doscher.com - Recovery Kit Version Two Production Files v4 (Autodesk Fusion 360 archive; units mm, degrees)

design "doscher.com - Recovery Kit Version Two Production Files" references "6168T59_Push-In Signal Power Connectors(1)", "6886K111_Flush-Mount 16 mm Panel-Mount Push-Button Switch", "1422N13_Panel-Mount Data Adapter"
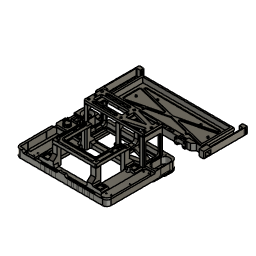
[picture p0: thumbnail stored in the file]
parameter "d91" = 8.5
parameter "d92" = -6
parameter "d93" = 0
parameter "d94" = 3
parameter "d95" = 2
parameter "d96" = 3
parameter "d97" = 0
parameter "d98" = 11
parameter "d99" = -35
parameter "d100" = 0
parameter "d101" = -8.951
parameter "d102" = 7
parameter "d103" = -3
parameter "d104" = 0
parameter "d105" = -35
parameter "d106" = 2.8
parameter "d107" = 2.8
parameter "d108" = -70
parameter "d109" = 0
parameter "d110" = 2
parameter "d111" = 2
parameter "d112" = -10
parameter "d113" = 0
parameter "d114" = -5
parameter "d115" = 0
parameter "d116" = -10
parameter "d117" = 0
parameter "d118" = -10
parameter "d119" = 0
parameter "d120" = -2
parameter "d121" = 0
parameter "d122" = 5
parameter "d124" = 0.1
parameter "d126" = 0.1
parameter "d128" = 0.1
parameter "d129" = -4
parameter "d130" = 0
parameter "d131" = 6
parameter "d132" = 0
parameter "d133" = 6
parameter "d134" = 0
parameter "d135" = -3
parameter "d136" = 0
parameter "d137" = 2
parameter "d138" = 0
parameter "d139" = 2
parameter "d140" = 0
parameter "d141" = -4
parameter "d142" = 0
parameter "d143" = 2
parameter "d144" = 0
parameter "d145" = -35
parameter "d146" = 3.8
parameter "d147" = -35
parameter "d148" = 3.8
parameter "d149" = 2.8
parameter "d150" = -20
parameter "d151" = 0
parameter "d152" = 2.8
parameter "d153" = -15
parameter "d154" = 0
parameter "d155" = -54
parameter "d156" = 2.8
parameter "d157" = 51
parameter "d158" = 2.8
parameter "d159" = -54
parameter "d160" = 2.8
parameter "d161" = 62
parameter "d162" = 2.8
parameter "d163" = 90
parameter "d164" = 3.8
parameter "d165" = 100
parameter "d166" = 3.8
parameter "d167" = 2.8
parameter "d168" = -57
parameter "d169" = 0
parameter "d170" = 2
parameter "d171" = 1
parameter "d172" = 20
parameter "d173" = 1
parameter "d174" = 20
parameter "d175" = 1
parameter "d176" = -19
parameter "d177" = 0
parameter "d178" = 59
parameter "d179" = 49.5
parameter "d180" = 59
parameter "d182" = 3
parameter "d183" = 3
parameter "d184" = 9
parameter "d185" = 55.5
parameter "d186" = 3
parameter "d187" = 55.5
parameter "d188" = 10
parameter "d189" = 0
parameter "d190" = 3
parameter "d191" = 3
parameter "d192" = 3
parameter "d193" = 3
parameter "d194" = 3
parameter "d195" = 0
parameter "d196" = -6
parameter "d197" = 0
parameter "d198" = -3
parameter "d199" = 0
parameter "d201" = 3
parameter "d203" = 2
parameter "d204" = 2
parameter "d205" = 5
parameter "d206" = 10
parameter "d207" = 5
parameter "d208" = 10
parameter "d209" = 10
parameter "d210" = 10
parameter "d211" = 10
parameter "d212" = 10
parameter "d213" = 2.8
parameter "d214" = 2.8
parameter "d215" = 2.8
parameter "d216" = -84
parameter "d217" = 0
parameter "d218" = 1
parameter "d219" = 0
parameter "d220" = 2
parameter "d221" = 2
parameter "d222" = 2
parameter "d223" = 2
parameter "d224" = -2
parameter "d225" = -2
parameter "d226" = -2
parameter "d227" = 2.8
parameter "d228" = -2
parameter "d229" = 2.8
parameter "d230" = -2
parameter "d231" = 2.8
parameter "d233" = 7.5
parameter "d235" = 7.5
parameter "d237" = 3.25
parameter "d238" = -1
parameter "d239" = 2.8
parameter "d240" = -1
parameter "d241" = 2.8
parameter "d243" = 8
parameter "d245" = 8
parameter "d246" = -1
parameter "d247" = 2.8
parameter "d248" = -15
parameter "d249" = 0
parameter "d251" = 0.1
parameter "d252" = 16
parameter "d253" = 4
parameter "d254" = 3
parameter "d255" = 8
parameter "d256" = -5
parameter "d257" = 0
parameter "d259" = 1
parameter "d261" = 1
parameter "d262" = 51.5
parameter "d263" = 158
parameter "d264" = 2
parameter "d265" = 0
parameter "d266" = 10
parameter "d267" = 26
parameter "d268" = -4
parameter "d269" = 0
parameter "d270" = 1
parameter "d271" = 3
parameter "d272" = 50
parameter "d273" = 2.8
parameter "d274" = 24
parameter "d275" = 3
parameter "d276" = 50
parameter "d277" = 3
parameter "d278" = 50
parameter "d279" = 3
parameter "d280" = 50
parameter "d281" = 3
parameter "d282" = 26
parameter "d283" = 3
parameter "d284" = 50
parameter "d285" = 3
parameter "d286" = 50
parameter "d287" = 3
parameter "d288" = 30
parameter "d289" = 3
parameter "d290" = 50
parameter "d291" = 3
parameter "d292" = 10
parameter "d293" = 10
parameter "d294" = 10
parameter "d295" = 10
parameter "d296" = 10
parameter "d297" = 10
parameter "d298" = 10
parameter "d299" = 10
parameter "d300" = 10
parameter "d301" = 10
parameter "d302" = 10
parameter "d303" = 10
parameter "d304" = 10
parameter "d305" = 10
parameter "d306" = 10
parameter "d307" = 10
parameter "d308" = 10
parameter "d309" = 10
parameter "d310" = 3
parameter "d311" = -10
parameter "d312" = 0
parameter "d313" = 1
parameter "d314" = 0
parameter "d315" = 2
parameter "d316" = 2
parameter "d317" = 3
parameter "d318" = 0
parameter "d319" = -3
parameter "d320" = 6
parameter "d321" = -3
parameter "d322" = 6
parameter "d323" = -3
parameter "d324" = 6
parameter "d325" = -3
parameter "d326" = 6
parameter "d327" = -3
parameter "d328" = 6
parameter "d329" = -3
parameter "d330" = 6
parameter "d331" = -3
parameter "d332" = 6
parameter "d333" = -3
parameter "d334" = 6
parameter "d335" = -3
parameter "d336" = 6
parameter "d337" = -3
parameter "d338" = 0
parameter "d339" = 2
parameter "d340" = 2
parameter "d341" = 0
parameter "d343" = 0.1
parameter "d344" = 1
parameter "d345" = 0
parameter "d346" = 59
parameter "d347" = 0
parameter "d348" = 9
parameter "d349" = 0
parameter "d350" = 6
parameter "d351" = 0
parameter "d352" = -13
parameter "d353" = 0
parameter "d355" = 1
parameter "d357" = 2
parameter "d358" = 3
parameter "d359" = 3
parameter "d360" = 3
parameter "d361" = 3
parameter "d362" = 3
parameter "d363" = 6
parameter "d364" = 6
parameter "d365" = 6
parameter "d366" = 6
parameter "d367" = -2
parameter "d368" = 0
parameter "d369" = 1
parameter "d370" = 0
parameter "d371" = 0.6
parameter "d372" = 0
parameter "d373" = 158.5
parameter "d374" = 52
parameter "d375" = -20
parameter "d376" = 0
parameter "d377" = 0.6
parameter "d378" = 0
parameter "d379" = 4
parameter "d380" = 0
parameter "d381" = 4
parameter "d382" = 0
parameter "d383" = -0.5
parameter "d384" = 0
parameter "d385" = -0.5
parameter "d386" = 0
parameter "d387" = 2
parameter "d388" = 2
parameter "d389" = 2
parameter "d390" = 2
parameter "d391" = -0.5
parameter "d392" = -0.5
parameter "d393" = -0.5
parameter "d394" = 2
parameter "d395" = 0
parameter "d396" = 2
parameter "d397" = 0
parameter "d398" = 15
parameter "d399" = 15
parameter "d400" = 3
parameter "d401" = 42
parameter "d402" = 0
parameter "d403" = 3
parameter "d404" = -20
parameter "d405" = 0
parameter "d406" = 46
parameter "d407" = 59
parameter "d408" = -2
parameter "d409" = 0
parameter "d410" = 3
parameter "d411" = -41
parameter "d412" = 27.5
parameter "d413" = -29
parameter "d414" = 2.8
parameter "d415" = -51
parameter "d416" = 2.8
parameter "d417" = -43
parameter "d418" = 2.8
parameter "d419" = -42
parameter "d420" = 2.8
parameter "d421" = -59
parameter "d422" = 2.8
parameter "d423" = -59
parameter "d424" = 2.8
parameter "d425" = -37
parameter "d426" = 3
parameter "d427" = -26
parameter "d428" = 3
parameter "d429" = -25
parameter "d430" = 3
parameter "d431" = 45
parameter "d432" = 135
parameter "d433" = 140
parameter "d434" = -10
parameter "d435" = 0
parameter "d436" = -1
parameter "d437" = 0
parameter "d438" = 2.299
parameter "d439" = -2
parameter "d440" = 0
parameter "d441" = 1
parameter "d442" = 0
parameter "d443" = 3
parameter "d444" = 3
parameter "d445" = 3
parameter "d446" = 0
parameter "d447" = 4
parameter "d448" = 2
parameter "d449" = -15
parameter "d450" = 0
parameter "d451" = 2
parameter "d452" = 3
parameter "d453" = 0
parameter "d454" = 3
parameter "d455" = 5.5
parameter "d456" = 2
parameter "d457" = 5.5
parameter "d458" = -1
parameter "d459" = 0
parameter "d460" = 2
parameter "d461" = 5.5
parameter "d462" = -10
parameter "d463" = 3
parameter "d464" = -10
parameter "d465" = 3
parameter "d466" = -10
parameter "d467" = 3
parameter "d468" = 35
parameter "d469" = 0
parameter "d470" = 14
parameter "d471" = 23
parameter "d472" = 43
parameter "d473" = 23
parameter "d474" = -7
parameter "d475" = 0
parameter "d476" = -15
parameter "d477" = 15
parameter "d478" = 0
parameter "d479" = 2
parameter "d480" = -10
parameter "d481" = 0
parameter "d482" = -2
parameter "d483" = 0
parameter "d484" = 2
parameter "d485" = 15
parameter "d486" = -2
parameter "d487" = 0
parameter "d489" = 0.1
parameter "d490" = 43
parameter "d491" = 3
parameter "d492" = 30
parameter "d493" = 3
parameter "d494" = 39
parameter "d495" = 3
parameter "d496" = -22
parameter "d497" = 36
parameter "d498" = 15.5
parameter "d499" = 31
parameter "d500" = 15.5
parameter "d501" = 41
parameter "d502" = 2.8
parameter "d503" = 5
parameter "d504" = 52
parameter "d505" = 2.8
parameter "d506" = -39
parameter "d507" = 0
parameter "d508" = -3
parameter "d509" = 0
parameter "d510" = -5
parameter "d511" = 0
parameter "d512" = 10
parameter "d513" = 3
parameter "d514" = 0
parameter "d515" = -3
parameter "d516" = 5.5
parameter "d517" = -3
parameter "d518" = 5.5
parameter "d519" = -3
parameter "d520" = 5.5
parameter "d521" = 3
parameter "d522" = 8
parameter "d523" = 3
parameter "d524" = 0
parameter "d525" = 3
parameter "d526" = -3
parameter "d527" = 5.5
parameter "d528" = -3
parameter "d529" = 5.5
parameter "d530" = -3
parameter "d531" = 5.5
parameter "d532" = 3
parameter "d533" = 5.5
parameter "d534" = 2
parameter "d535" = 0
parameter "d536" = -2
parameter "d537" = 1.5
parameter "d538" = 1.5
parameter "d539" = -15
parameter "d540" = 0
parameter "d541" = 13
parameter "d542" = 1.5
parameter "d543" = 1.5
parameter "d544" = -15
parameter "d545" = 0
parameter "d546" = 2
parameter "d547" = 0
parameter "d548" = 2
parameter "d549" = 1.5
parameter "d550" = 13
parameter "d551" = 1.5
parameter "d552" = 13
parameter "d553" = 3
parameter "d554" = 3
parameter "d555" = -18
parameter "d556" = 0
parameter "d557" = -20
parameter "d558" = 0
parameter "d559" = 50
parameter "d560" = 2.8
parameter "d561" = 45
parameter "d562" = 2.8
parameter "d563" = 7.39
parameter "d564" = 7.39
parameter "d565" = 2.8
parameter "d566" = 2.8
parameter "d567" = -63
parameter "d568" = 0
parameter "d569" = 35
parameter "d570" = 5.5
parameter "d571" = -1
parameter "d572" = -1
parameter "d573" = -1
parameter "d574" = -3
parameter "d575" = 3
parameter "d576" = 0
parameter "d577" = 2
parameter "d578" = 2
parameter "d579" = -57
parameter "d580" = 0
parameter "d581" = 6
parameter "d582" = 0
parameter "d583" = 50
parameter "d584" = 2.8
parameter "d585" = 49
parameter "d586" = 2.8
parameter "d587" = 7
parameter "d589" = 5.7
parameter "d590" = 10.8
parameter "d591" = -44
parameter "d592" = 0
parameter "d593" = 1.5
parameter "d594" = 0
parameter "d595" = 1
parameter "d596" = 0
parameter "d597" = 2
parameter "d598" = 3
parameter "d599" = 3.5
parameter "d600" = 2.8
parameter "d601" = 3.5
parameter "d602" = 2.8
parameter "d603" = -58
parameter "d604" = 0
parameter "d605" = 3
parameter "d606" = 35
parameter "d607" = 27.5
parameter "d608" = 42
parameter "d609" = 2.8
parameter "d610" = 42
parameter "d611" = 2.8
parameter "d612" = 37
parameter "d613" = 2.8
parameter "d614" = 42
parameter "d615" = 2.8
parameter "d616" = 18
parameter "d617" = -4
parameter "d618" = 0
parameter "d619" = 15
parameter "d620" = -6
parameter "d621" = 0
parameter "d622" = 40
parameter "d623" = 27.5
parameter "d624" = -7
parameter "d625" = 0
parameter "d626" = 3
parameter "d627" = -60
parameter "d628" = 2.8
parameter "d629" = -3
parameter "d630" = 5.5
parameter "d631" = -3
parameter "d632" = 5.5
parameter "d633" = 3
parameter "d634" = 12
parameter "d635" = 0
parameter "d636" = 8
parameter "d637" = -26
parameter "d638" = 2.8
parameter "d639" = 5
parameter "d640" = 0
parameter "d641" = 5
parameter "d642" = 5
parameter "d643" = -50
parameter "d644" = 11.1
parameter "d645" = -2
parameter "d646" = 10
parameter "d647" = 0
parameter "d648" = -1.5
parameter "d649" = 0
parameter "d650" = 3
parameter "d651" = -20
parameter "d652" = 5
parameter "d653" = -10
parameter "d654" = 5
parameter "d655" = 29
parameter "d656" = 10
parameter "d657" = -5
parameter "d658" = 0
parameter "d659" = 1
parameter "d660" = 2
parameter "d661" = 3
parameter "d662" = 3
parameter "d663" = 5
parameter "d664" = 0
parameter "d665" = 5
parameter "d666" = 5
parameter "d667" = 0
parameter "d668" = 5
parameter "d669" = 5
parameter "d670" = 0
parameter "d671" = 5
parameter "d672" = 5
parameter "d673" = 0
parameter "d674" = 3
parameter "d675" = 3
parameter "d676" = 3
parameter "d678" = 0.1
parameter "d679" = -60
parameter "d680" = 0
parameter "d681" = 2
parameter "d682" = 1
parameter "d683" = 5
parameter "d684" = 0
parameter "d685" = 5
parameter "d686" = 1
parameter "d687" = -4
parameter "d688" = 2.8
parameter "d689" = -4
parameter "d690" = 2.8
parameter "d691" = -4
parameter "d692" = 2.8
parameter "d693" = -4
parameter "d694" = 2.8
parameter "d695" = 5
parameter "d696" = 0
parameter "d697" = 5
parameter "d698" = 0
parameter "d699" = 5
parameter "d700" = 5
parameter "d701" = -3
parameter "d702" = 2.8
parameter "d703" = -3
parameter "d704" = 2.8
parameter "d705" = -3
parameter "d706" = 2.8
parameter "d707" = -3
parameter "d708" = 2.8
parameter "d709" = -2
parameter "d710" = 0
parameter "d711" = -2
parameter "d712" = 0
parameter "d713" = -2
parameter "d714" = 0
parameter "d715" = -2
parameter "d716" = 0
parameter "d717" = 225
parameter "d718" = 74
parameter "d719" = 36.5
parameter "d720" = 36.5
parameter "d721" = 17.9
parameter "d722" = 17.9
parameter "d723" = 56
parameter "d724" = 56
parameter "d725" = 17.5
parameter "d726" = 17.5
parameter "d727" = 56
parameter "d728" = 56
parameter "d729" = 17.5
parameter "d730" = 17.5
parameter "d731" = 1.8
parameter "d732" = 1.8
parameter "d733" = 1.8
parameter "d734" = 1.8
parameter "d735" = 1.8
parameter "d736" = 1.8
parameter "d737" = -5
parameter "d738" = 7
parameter "d739" = 7
parameter "d740" = 7
parameter "d741" = 7
parameter "d742" = 7
parameter "d743" = 7
parameter "d744" = 5
parameter "d745" = 0
parameter "d746" = -4
parameter "d747" = 3
parameter "d748" = 0
parameter "d749" = 2
parameter "d750" = 7
parameter "d751" = 2
parameter "d752" = 7
parameter "d753" = 2
parameter "d754" = 7
parameter "d755" = 2
parameter "d756" = 7
parameter "d757" = 2
parameter "d758" = 7
parameter "d759" = 2
parameter "d760" = 7
parameter "d761" = -50
parameter "d762" = 1.8
parameter "d763" = -50
parameter "d764" = 1.8
parameter "d765" = -50
parameter "d766" = 1.8
parameter "d767" = -80
parameter "d768" = 1.8
parameter "d769" = -50
parameter "d770" = 1.8
parameter "d771" = -50
parameter "d772" = 1.8
parameter "d773" = 1
parameter "d774" = -3
parameter "d775" = 0
parameter "d776" = 5
parameter "d777" = 0
parameter "d778" = 2
parameter "d779" = 115
parameter "d780" = 20
parameter "d781" = 2
parameter "d782" = 0
parameter "d783" = 10
parameter "d784" = 20
parameter "d785" = 0
parameter "d786" = 10
parameter "d787" = 0
parameter "d788" = -10
parameter "d789" = 0
parameter "d790" = 15
parameter "d791" = -12
parameter "d792" = 0
parameter "d794" = 2
parameter "d796" = 5
parameter "d797" = -5
parameter "d798" = 5
parameter "d799" = -27
parameter "d800" = 0
parameter "d802" = 0.1
parameter "d803" = 110
parameter "d804" = 0
parameter "d805" = 0
parameter "d806" = -1
parameter "d807" = 2
parameter "d808" = 5
parameter "d809" = 0
parameter "d810" = -15
parameter "d811" = 0
parameter "d812" = 3
parameter "d813" = 1
parameter "d814" = -3
parameter "d815" = 0
parameter "d816" = -3
parameter "d817" = -50
parameter "d818" = 0
parameter "d820" = 0.1
parameter "d821" = -0.1
parameter "d822" = -0.1
parameter "d823" = 3
parameter "d824" = -0.5
parameter "d825" = 0
parameter "d826" = -0.5
parameter "d827" = 0
parameter "d828" = 33
parameter "d829" = 10.5
parameter "d830" = 7.8
parameter "d831" = -7
parameter "d832" = 0
parameter "d833" = 3.4
parameter "d834" = -9
parameter "d835" = 0
parameter "d836" = 0.5
parameter "d837" = 0
parameter "d838" = 0.5
parameter "d839" = 0
parameter "d840" = -2
parameter "d841" = 0
parameter "d842" = 23.5
parameter "d843" = 2
parameter "d844" = -7.5
parameter "d845" = 0
parameter "d846" = -2
parameter "d847" = 0
parameter "d848" = -2
parameter "d849" = 0
parameter "d850" = 23.5
parameter "d851" = 2
parameter "d852" = -5
parameter "d853" = 0
parameter "d854" = 1.9
parameter "d855" = 0
parameter "d856" = 1.9
parameter "d857" = 0
parameter "d858" = 23.5
parameter "d859" = 2
parameter "d860" = -20
parameter "d861" = 0
parameter "d862" = -2
parameter "d863" = 0
parameter "d864" = 23.5
parameter "d865" = 2
parameter "d866" = -10
parameter "d867" = 0
parameter "d868" = -2
parameter "d869" = 0
parameter "d870" = 5
parameter "d871" = 5
parameter "d872" = 5
parameter "d873" = 5
parameter "d874" = 2
parameter "d875" = 0
parameter "d876" = 7
parameter "d877" = 0
parameter "d878" = 7
parameter "d879" = 7
parameter "d880" = 7
parameter "d881" = 7
parameter "d882" = -7
parameter "d883" = 0
parameter "d884" = -15
parameter "d885" = 0
parameter "d886" = 7
parameter "d887" = 7
parameter "d888" = 4
parameter "d889" = -10
parameter "d890" = 0
parameter "d891" = 7
parameter "d892" = 7
parameter "d893" = 2.3
parameter "d894" = -5
parameter "d895" = 0
parameter "d896" = 7
parameter "d897" = 7
parameter "d898" = 2.3
parameter "d899" = -5
parameter "d900" = 0
parameter "d901" = 7
parameter "d902" = 1.5
parameter "d903" = -2
parameter "d904" = 2
parameter "d905" = 0
parameter "d906" = 0
parameter "d907" = -2
parameter "d908" = 2
parameter "d909" = 2
parameter "d910" = -7
parameter "d911" = 0
parameter "d912" = -2
parameter "d913" = 0
parameter "d914" = -2
parameter "d915" = 0
parameter "d916" = 1.25
parameter "d917" = 0
parameter "d918" = 1.25
parameter "d919" = 0
parameter "d920" = -1
parameter "d921" = -1
parameter "d922" = 0
parameter "d923" = 0
parameter "d924" = -1
parameter "d925" = 0
parameter "d926" = 1
parameter "d927" = 0
parameter "d928" = 0
parameter "d929" = -10
parameter "d930" = 0
parameter "d931" = -50
parameter "d932" = 2.1
parameter "d933" = -50
parameter "d934" = 2.1
parameter "d935" = -50
parameter "d936" = 2.1
parameter "d937" = -50
parameter "d938" = 2.1
parameter "d939" = -50
parameter "d940" = 2.1
parameter "d941" = -50
parameter "d942" = 2.1
parameter "d943" = 1
parameter "d944" = 0
parameter "d945" = 600
parameter "d946" = 0
parameter "d952" = -96
parameter "d953" = 1
parameter "d954" = 40
parameter "d955" = 0
parameter "d956" = 0.1
parameter "d957" = -1.5
parameter "d958" = 0
parameter "d959" = -200
parameter "d960" = 1
parameter "d961" = -0.3
parameter "d962" = -1
parameter "d963" = 0
parameter "d964" = -100
parameter "d965" = 1
parameter "d966" = -500
parameter "d967" = 1
parameter "d968" = -500
parameter "d969" = 1
parameter "d970" = 0
parameter "d971" = 0
parameter "d972" = 50
parameter "d973" = -0.1
parameter "d974" = -1.5
parameter "d975" = 0
parameter "d976" = -0.1
parameter "d977" = -1.5
parameter "d978" = 0
parameter "d979" = 1.2
parameter "d980" = 0
parameter "d981" = 0
parameter "d982" = 0.1
parameter "d983" = -1
parameter "d984" = 0
parameter "d985" = 0
parameter "d986" = 0
parameter "d987" = 65
parameter "d991" = -1.5
parameter "d992" = 2
parameter "d993" = 0
parameter "d997" = 1
parameter "d998" = 0
parameter "d999" = 0
parameter "d1000" = -10
parameter "d1001" = 2.2
parameter "d1002" = -10
parameter "d1003" = 2.2
parameter "d1006" = -10
parameter "d1007" = 2.2
parameter "d1008" = -10
parameter "d1009" = 2.2
parameter "d1010" = -10
parameter "d1011" = 2.2
parameter "d1012" = 5
parameter "d1013" = 5
parameter "d1014" = 5
parameter "d1015" = 5
parameter "d1016" = 5
parameter "d1017" = 5
parameter "d1018" = 2
parameter "d1019" = 0
parameter "d1020" = 1.5
parameter "d1021" = 0
parameter "d1022" = -9
parameter "d1023" = 0
parameter "d1024" = 11
parameter "d1025" = 2
parameter "d1026" = 8
parameter "d1027" = 0
parameter "d1028" = 2
parameter "d1029" = 0
parameter "d1030" = -2
parameter "d1031" = 1
parameter "d1032" = 0
parameter "d1033" = 8
parameter "d1034" = 0
parameter "d1035" = 17
parameter "d1036" = 8
parameter "d1037" = 0
parameter "d1038" = 8
parameter "d1039" = 8
parameter "d1040" = 8
parameter "d1041" = 8
parameter "d1042" = 8
parameter "d1043" = 3.8
parameter "d1044" = 3.8
parameter "d1045" = -5
parameter "d1046" = 0
parameter "d1047" = 2
parameter "d1048" = 2
parameter "d1049" = 2
parameter "d1050" = 0
parameter "d1051" = 2
parameter "d1052" = 15
parameter "d1053" = 4
parameter "d1054" = 15
parameter "d1055" = 5
parameter "d1056" = 4
parameter "d1057" = 15
parameter "d1058" = 4
parameter "d1059" = 15
parameter "d1060" = 4
parameter "d1061" = 5
parameter "d1062" = 5
parameter "d1063" = 15
parameter "d1064" = 4
parameter "d1065" = 5
parameter "d1066" = 5
parameter "d1067" = 4
parameter "d1068" = 5
parameter "d1069" = 4
parameter "d1070" = 5
parameter "d1071" = 4
parameter "d1072" = 5
parameter "d1073" = 4
parameter "d1074" = 5
parameter "d1075" = -30
parameter "d1076" = 0
parameter "d1077" = 2
parameter "d1078" = 1
parameter "d1079" = 1
parameter "d1080" = 8
parameter "d1081" = 8
parameter "d1082" = 8
parameter "d1083" = 8
parameter "d1084" = 3.8
parameter "d1085" = 3.8
parameter "d1086" = -5
parameter "d1087" = 0
parameter "d1088" = 5
parameter "d1089" = 0
parameter "d1090" = 19
parameter "d1091" = 11.5
parameter "d1092" = 3.8
parameter "d1093" = 3.8
parameter "d1094" = -5
parameter "d1095" = 0
parameter "d1096" = 2
parameter "d1097" = -50
parameter "d1098" = 2.5
parameter "d1099" = -50
parameter "d1100" = 2.5
parameter "d1101" = 2
parameter "d1102" = 10
parameter "d1103" = 2
parameter "d1104" = 10
parameter "d1105" = -110
parameter "d1106" = 0
parameter "d1107" = 2
parameter "d1108" = 2
parameter "d1109" = 2
parameter "d1110" = -1
parameter "d1111" = 0
parameter "d1112" = 106
parameter "d1113" = 0
parameter "d1114" = 14
parameter "d1115" = 14
parameter "d1116" = 14
parameter "d1117" = 14
parameter "d1118" = 14
parameter "d1119" = 14
parameter "d1120" = 14
parameter "d1121" = 14
parameter "d1126" = 4
parameter "d1127" = 4
parameter "d1128" = 2
parameter "d1129" = 0
parameter "d1131" = 3
parameter "d1133" = 3
parameter "d1134" = 8
parameter "d1135" = 8
parameter "d1136" = 28.5
parameter "d1137" = 2
parameter "d1138" = 0.3
parameter "d1139" = 0.3
parameter "d1140" = 12
parameter "d1141" = 12
parameter "d1142" = 5
parameter "d1143" = 0
parameter "d1144" = 0
parameter "d1145" = 0
parameter "d1146" = 13
parameter "d1147" = 3
parameter "d1148" = 0
parameter "d1149" = 6.5
parameter "d1150" = 0
parameter "d1151" = -0.336
parameter "d1152" = 0
parameter "d1153" = -0.305
parameter "d1154" = 0
parameter "d1155" = 1
parameter "d1156" = -6
parameter "d1157" = 0
parameter "d1158" = 0
parameter "d1159" = -16
parameter "d1160" = 0
parameter "d1161" = 2
parameter "d1162" = 0
parameter "d1163" = 3
parameter "d1164" = 0
parameter "d1165" = 23
parameter "d1166" = 4
parameter "d1167" = 24
parameter "d1168" = 4
parameter "d1169" = 22
parameter "d1170" = 4
parameter "d1171" = 25
parameter "d1172" = 4
parameter "d1173" = 0
parameter "d1174" = 16
parameter "d1175" = 0
parameter "d1176" = -1
parameter "d1177" = 0
parameter "d1178" = -2
parameter "d1179" = 0
parameter "d1180" = 2
parameter "d1181" = -3
parameter "d1182" = 0
parameter "d1183" = 24
parameter "d1184" = 0
parameter "d1185" = 13
parameter "d1186" = 1
parameter "d1187" = 2
parameter "d1188" = 0
parameter "d1189" = 2
parameter "d1190" = 7.8
parameter "d1191" = -6
parameter "d1192" = 3.1
base_feature "Base Feature1" bodies "doscher.com - Recovery Kit Version Two Display Frame", "doscher.com - Recovery Kit Version Two Display Bracker Right", "doscher.com - Recovery Kit Version Two Display Bracket Left", "doscher.com - Recovery Kit Version Two Battery Short End", "doscher.com - Recovery Kit Version Two Battery Middle", "doscher.com - Recovery Kit Version Two Battery Long End", "doscher.com - Recovery Kit Version Two Battery Rear", "doscher.com - Recovery Kit Version Two Battery Front"
component_insert "Component Insert1"
component_insert "Component Insert2"
component_insert "Component Insert3"
base_feature "Base Feature1"
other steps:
create_component "CreateComponent1"
named bodies: "doscher.com - Recovery Kit Version Two Display Frame", "doscher.com - Recovery Kit Version Two Display Bracker Right", "doscher.com - Recovery Kit Version Two Display Bracket Left", "doscher.com - Recovery Kit Version Two Battery Short End", "doscher.com - Recovery Kit Version Two Battery Middle", "doscher.com - Recovery Kit Version Two Battery Long End", "doscher.com - Recovery Kit Version Two Battery Rear", "doscher.com - Recovery Kit Version Two Battery Front", "doscher.com - Recovery Kit Version Two Battery Clip Left", "doscher.com - Recovery Kit Version Two Battery Clip Right", "doscher.com - Recovery Kit Version Two GPIO Tray", "doscher.com - Recovery Kit Version Two - Primary Frame", "doscher.com - Recovery Kit Version Two Planck v7 Keyboard Tray", "doscher.com - Recovery Kit Version Two USB-C Keyboard Brace"

design "6168T59_Push-In Signal Power Connectors(1)"
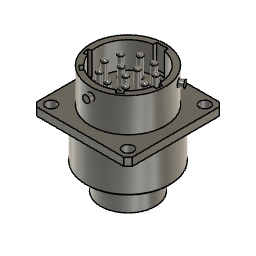
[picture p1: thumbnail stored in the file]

design "1422N13_Panel-Mount Data Adapter"
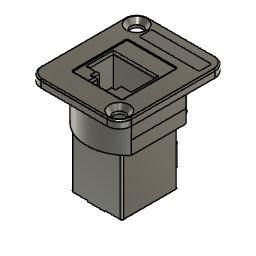
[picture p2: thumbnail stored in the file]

design "6886K111_Flush-Mount 16 mm Panel-Mount Push-Button Switch"
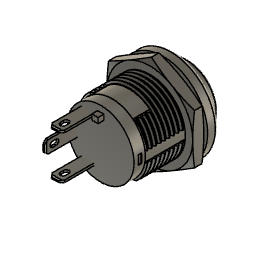
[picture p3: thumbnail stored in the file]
